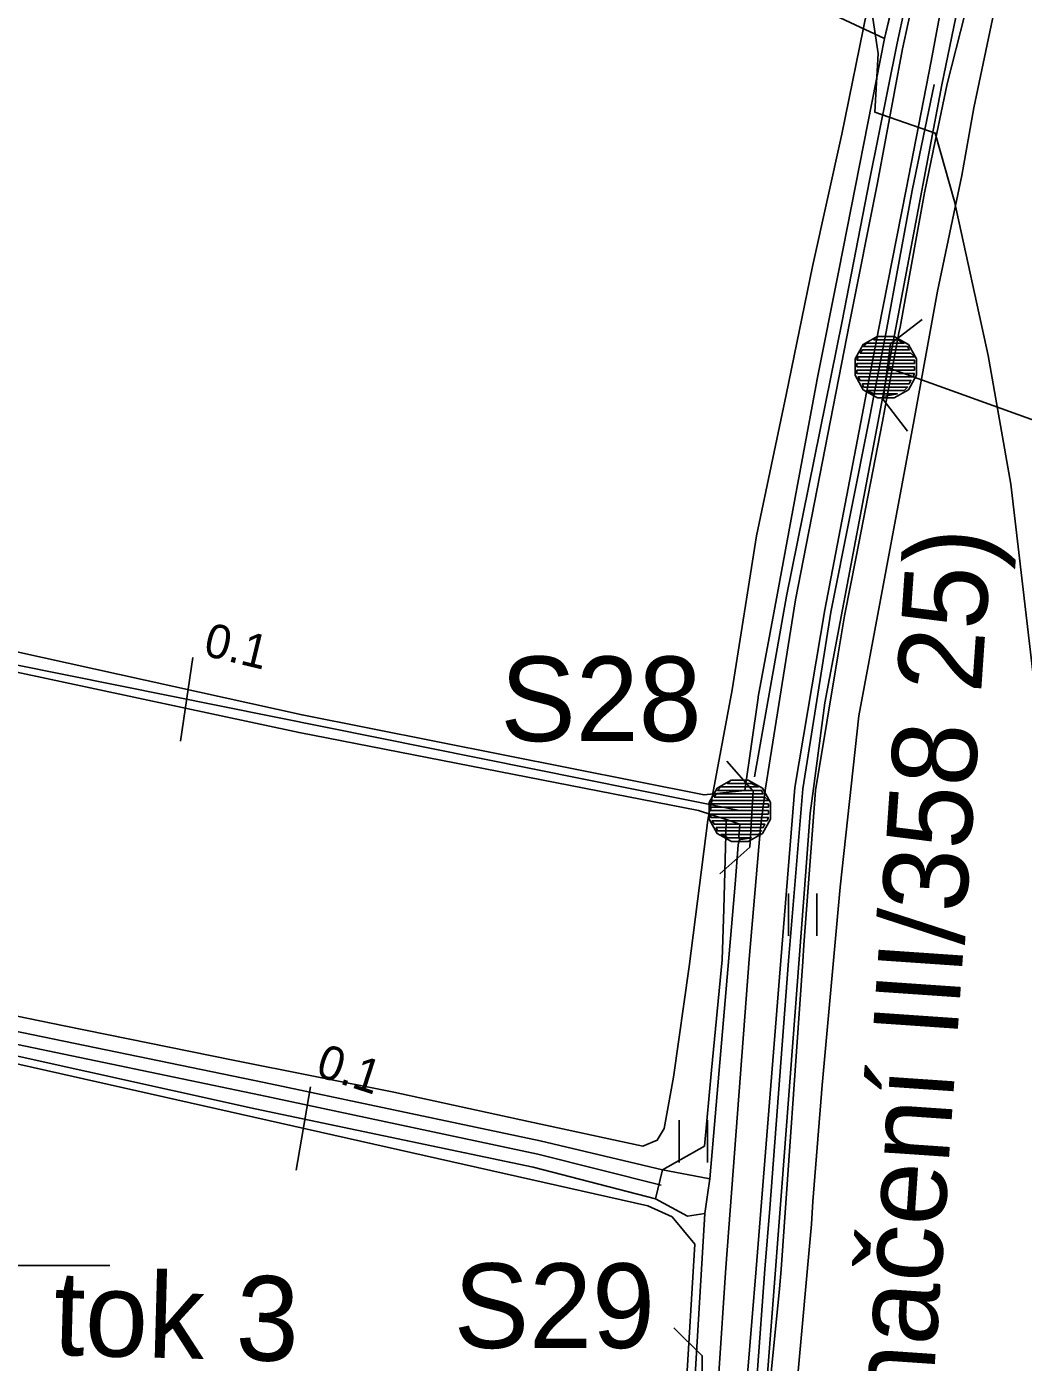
# Model space of a CAD drawing. Extents: x -645676 to -642474, y -1077513 to -1072613.
# Drawn here: x -644732.8 to -644556.1, y -1075319 to -1075082.2 of the extents above; entities that cross this region are included whole.
import ezdxf

# ---------------------------------------------------------------- set-up
doc = ezdxf.new("R2010")
doc.units = 0
for name, color, linetype in [('KULTURY_STAV', 7, 'Continuous'), ('KULTURY_ZNACKY', 7, 'Continuous'), ('NERESENE_POZEMKY', 7, 'Continuous'), ('Obvod_KP_', 7, 'Continuous'), ('OBVOD_PU', 7, 'Continuous'), ('P__kop___st_vaj_c_', 7, 'Continuous'), ('PC_NAVRH', 7, 'Continuous'), ('PC_OBJ_POPIS_NAVRH', 7, 'Continuous'), ('PC_OBJEKTY_NAVRH', 7, 'Continuous'), ('PC_STAN_NAVRH', 7, 'Continuous'), ('PLYNOVOD', 7, 'Continuous'), ('Popis_silnice_II__a_III__t__dy', 7, 'Continuous'), ('SDELOVACI', 7, 'Continuous'), ('Silnice_II__t__dy_a_III__t__dy', 7, 'Continuous'), ('Vodn__plocha___st_vaj_c_', 7, 'Continuous'), ('Vodn__tok', 7, 'Continuous'), ('VRSTEVNICE', 7, 'Continuous')]:
    doc.layers.add(name, color=color, linetype=linetype)

# ---------------------------------------------------------------- blocks, each defined once
blk = doc.blocks.new('$406')
blk.add_lwpolyline([(-0.19, 0.72), (0.2, 0.72), (0.54, 0.53), (0.73, 0.19), (0.73, -0.2), (0.54, -0.54), (0.2, -0.73), (-0.19, -0.73), (-0.53, -0.54), (-0.72, -0.2), (-0.72, 0.19), (-0.53, 0.53), (-0.2, 0.72), (-0.28, 0.64), (0.28, 0.64), (0.44, 0.56), (-0.44, 0.56), (-0.52, 0.48), (0.52, 0.48), (0.56, 0.4), (-0.55, 0.4), (-0.6, 0.32), (0.6, 0.32), (0.68, 0.24), (-0.59, 0.24), (-0.65, 0.24), (-0.68, 0.16), (0.59, 0.16), (0.68, 0.16), (0.68, 0.08), (-0.59, 0.08), (-0.68, 0.08), (-0.68, 0), (0.59, 0), (0.68, 0), (0.68, -0.08), (-0.59, -0.08), (-0.68, -0.08), (-0.68, -0.16), (0.59, -0.16), (0.68, -0.16), (0.65, -0.24), (-0.62, -0.24), (-0.65, -0.24), (-0.6, -0.32), (0.6, -0.32), (0.56, -0.4), (-0.55, -0.4), (-0.52, -0.48), (0.52, -0.48), (0.44, -0.56), (-0.44, -0.56), (-0.28, -0.64), (0.28, -0.64), (-0.02, -0.69)])
blk = doc.blocks.new('$944')
blk.add_line((0, 1.5), (0, -1.5))
blk = doc.blocks.new('8$0300')
for p, q in [((-7.5, 0), (-1.5, 0)), ((1.5, 0), (7.5, 0))]:
    blk.add_line(p, q)
blk = doc.blocks.new('3$0600')
for p, q in [((-0.5, 1.5), (-0.5, 0)), ((0.5, 0), (0.5, 1.5))]:
    blk.add_line(p, q)
blk = doc.blocks.new('$935')
blk.add_lwpolyline([(-2, -1), (-1, 0), (1, 0), (2, -1)])

msp = doc.modelspace()

# ---------------------------------------------------------------- linework, layer by layer
at = {"layer": 'KULTURY_STAV'}
for points in [[(-644641.24, -1075565.84), (-644614.92, -1075468.8), (-644611.62, -1075449.05), (-644602.57, -1075335.69), (-644598.94, -1075287.94), (-644594.67, -1075231.99), (-644593.88, -1075221.64), (-644593.31, -1075217.27), (-644591.32, -1075202.08), (-644570.53, -1075092.51), (-644563.77, -1075059.63)], [(-644563.77, -1075059.63), (-644570.53, -1075092.51), (-644591.32, -1075202.08), (-644593.31, -1075217.27), (-644593.88, -1075221.64), (-644594.67, -1075231.99), (-644598.94, -1075287.94), (-644602.57, -1075335.69), (-644611.62, -1075449.05), (-644614.92, -1075468.8), (-644641.24, -1075565.84)], [(-644563.36, -1075067.72), (-644569.63, -1075092.35), (-644571.75, -1075102.52), (-644573.65, -1075111.67), (-644575.07, -1075119.48), (-644577.96, -1075135.48), (-644578.15, -1075136.51), (-644578.57, -1075138.76), (-644581.06, -1075152.22), (-644585.75, -1075176.19), (-644587.8, -1075186.68), (-644588.91, -1075193.38), (-644592.93, -1075217.6), (-644595, -1075244.96), (-644595.22, -1075247.9), (-644599.01, -1075302.53), (-644599.35, -1075305.97), (-644600.88, -1075321.39)], [(-644600.88, -1075321.39), (-644599.35, -1075305.97), (-644599.01, -1075302.53), (-644595.22, -1075247.9), (-644595, -1075244.96), (-644592.93, -1075217.6), (-644588.91, -1075193.38), (-644587.8, -1075186.68), (-644585.75, -1075176.19), (-644581.06, -1075152.22), (-644578.57, -1075138.76), (-644578.15, -1075136.51), (-644577.96, -1075135.48), (-644575.07, -1075119.48), (-644573.65, -1075111.67), (-644571.75, -1075102.52), (-644569.63, -1075092.35), (-644563.36, -1075067.72)], [(-644734.54, -1075193.01), (-644683.98, -1075204.21), (-644612.72, -1075218.41), (-644605.49, -1075217.61), (-644603.14, -1075201.2), (-644603.12, -1075201.03), (-644599.69, -1075182.62), (-644596.24, -1075164.08), (-644592.7, -1075145.05), (-644592.69, -1075145.02), (-644588.83, -1075125.47), (-644580.71, -1075084.33), (-644577.57, -1075071.27)], [(-644577.57, -1075071.27), (-644580.71, -1075084.33), (-644588.83, -1075125.47), (-644592.69, -1075145.02), (-644592.7, -1075145.05), (-644596.24, -1075164.08), (-644599.69, -1075182.62), (-644603.12, -1075201.03), (-644603.14, -1075201.2), (-644605.49, -1075217.61), (-644612.72, -1075218.41), (-644683.98, -1075204.21), (-644734.54, -1075193.01)], [(-644735.38, -1075196.48), (-644684.51, -1075207.35), (-644613.68, -1075221.14), (-644608.8, -1075222.77), (-644608.87, -1075225.5), (-644609.23, -1075238.59), (-644609.48, -1075247.63), (-644611.37, -1075267.21), (-644612.66, -1075280.65), (-644620.07, -1075284.83), (-644641.76, -1075279.73), (-644690.73, -1075269.38), (-644741.2, -1075258.95)], [(-644616.89, -1075364.66), (-644612.56, -1075292.62), (-644612.08, -1075289.3), (-644611.68, -1075286.48), (-644607.21, -1075234.23), (-644606.65, -1075227.27), (-644606.36, -1075226.01), (-644606.54, -1075225.97), (-644606.35, -1075223.59), (-644608.8, -1075222.77), (-644613.68, -1075221.14), (-644684.51, -1075207.35), (-644735.38, -1075196.48)], [(-644608.8, -1075222.77), (-644606.35, -1075223.59), (-644606.54, -1075225.97), (-644606.36, -1075226.01), (-644606.65, -1075227.27), (-644607.21, -1075234.23), (-644611.68, -1075286.48), (-644611.99, -1075286.42), (-644620.07, -1075284.83), (-644612.66, -1075280.65), (-644611.37, -1075267.21), (-644609.48, -1075247.63), (-644609.23, -1075238.59), (-644608.87, -1075225.5), (-644608.8, -1075222.77)], [(-644741.2, -1075258.95), (-644690.73, -1075269.38), (-644641.76, -1075279.73), (-644620.07, -1075284.83), (-644611.99, -1075286.42), (-644611.68, -1075286.48), (-644612.08, -1075289.3), (-644612.56, -1075292.62), (-644615.66, -1075293.05), (-644621.33, -1075289.98), (-644643, -1075284.37), (-644655.11, -1075281.83), (-644692.33, -1075274.04), (-644736.8, -1075264.15)], [(-644851.08, -1075513.74), (-644779.52, -1075365.17), (-644777.84, -1075361.69), (-644757.68, -1075319.84), (-644760.71, -1075318.03), (-644746.53, -1075289.08), (-644737.59, -1075267.05), (-644736.8, -1075264.15), (-644692.33, -1075274.04), (-644655.11, -1075281.83), (-644643, -1075284.37), (-644621.33, -1075289.98), (-644615.66, -1075293.05), (-644612.56, -1075292.62), (-644616.89, -1075364.66), (-644616.92, -1075365.04), (-644618.52, -1075388.88), (-644622.17, -1075442.97), (-644622.41, -1075446.47), (-644626.67, -1075468.75), (-644631.36, -1075486.14), (-644660.63, -1075594.71)]]:
    msp.add_lwpolyline(points, dxfattribs=at)
at = {"layer": 'NERESENE_POZEMKY'}
msp.add_lwpolyline([(-644626.35, -1075010.4), (-644585.55, -1075012.13), (-644571.87, -1075012.71), (-644572.25, -1075021.71), (-644572.97, -1075038.79), (-644574.31, -1075056.6), (-644575.15, -1075060.82), (-644577.57, -1075071.27), (-644580.71, -1075084.33), (-644636.16, -1075058.45), (-644631.17, -1075036.69), (-644626.35, -1075010.4)], dxfattribs=at)
at = {"layer": 'Obvod_KP_'}
msp.add_lwpolyline([(-644626.35, -1075010.4), (-644631.17, -1075036.69), (-644636.16, -1075058.45), (-644580.71, -1075084.33), (-644575.15, -1075060.82), (-644574.31, -1075056.6), (-644572.97, -1075038.79), (-644572.25, -1075021.71), (-644571.87, -1075012.71)], close=True, dxfattribs=at)
at = {"layer": 'OBVOD_PU'}
msp.add_lwpolyline([(-644631.17, -1075036.69), (-644626.35, -1075010.4), (-644571.87, -1075012.71), (-644572.25, -1075021.71), (-644572.97, -1075038.79), (-644574.31, -1075056.6), (-644575.15, -1075060.82), (-644580.71, -1075084.33), (-644636.16, -1075058.45), (-644631.17, -1075036.69)], dxfattribs=at)
at = {"layer": 'P__kop___st_vaj_c_'}
for points in [[(-644575.75, -1075072.55), (-644578.46, -1075085.14), (-644583.36, -1075109.48), (-644588.22, -1075134.43), (-644598.09, -1075183.17), (-644603.76, -1075215.2)], [(-644655.14, -1075609.48), (-644653.46, -1075602.68), (-644648.86, -1075585.89), (-644635.16, -1075537.38), (-644617.89, -1075475.06), (-644613.54, -1075454.44), (-644610.92, -1075431.54), (-644607.37, -1075383.08), (-644603.3, -1075321.13), (-644601.93, -1075302.47), (-644601.06, -1075291.71), (-644597.72, -1075247.83), (-644595.19, -1075217.3), (-644590.26, -1075186), (-644583.34, -1075151.35), (-644580.44, -1075136.31), (-644575.79, -1075111.27), (-644571.92, -1075092.46)]]:
    msp.add_lwpolyline(points, dxfattribs=at)
at = {"layer": 'PC_NAVRH'}
for points in [[(-644606.41, -1075221.19), (-644836.11, -1075174.98), (-644844.56, -1075176.95), (-644881.27, -1075159.75), (-644907.13, -1075151.69), (-644922.26, -1075148.52), (-644947.39, -1075148.27), (-644953.49, -1075145.83), (-644953.49, -1075141.93), (-644894.93, -1074992.28), (-644829.47, -1074825.22)], [(-644615.94, -1075324.38), (-644614.35, -1075298.06), (-644618.37, -1075293.21), (-644622.69, -1075291.24), (-644738.79, -1075265.15), (-644794.9, -1075254.19), (-644881.17, -1075235.85), (-644890.64, -1075231.29), (-644935.93, -1075197.93), (-645029.58, -1075127.01), (-645122.98, -1075056.71), (-645236.69, -1074970.28), (-645321.72, -1074906.75)], [(-644580.52, -1075142.52), (-644416.45, -1075201.58), (-644177.18, -1075288.57), (-644151.16, -1075297.15), (-644120.06, -1075303.18), (-644089.59, -1075306.35), (-644066.74, -1075304.45)]]:
    msp.add_lwpolyline(points, dxfattribs=at)
at = {"layer": 'PLYNOVOD'}
msp.add_lwpolyline([(-644583.83, -1075079.56), (-644588.3, -1075101.28), (-644593.47, -1075124.74), (-644598.18, -1075147.46), (-644603.42, -1075172.45), (-644607.75, -1075199.77), (-644612.04, -1075222.9), (-644615.33, -1075248.82), (-644618.1, -1075268.44), (-644619.81, -1075277.52), (-644621, -1075279.62), (-644623.56, -1075280.66), (-644643.86, -1075276.28), (-644667.72, -1075271.06), (-644696.22, -1075265.41), (-644726.18, -1075259.33), (-644751.5, -1075254.12)], dxfattribs=at)
at = {"layer": 'SDELOVACI'}
msp.add_lwpolyline([(-644560.38, -1075075.22), (-644564.89, -1075096.59), (-644567.03, -1075108.6), (-644571.32, -1075129.12), (-644575.46, -1075151.85), (-644577.56, -1075163.27), (-644585.27, -1075204.39), (-644588.56, -1075234.74), (-644591.74, -1075269.83), (-644593.41, -1075290.49), (-644593.66, -1075294.47), (-644596.25, -1075323.14), (-644596.67, -1075334.53), (-644597.63, -1075356.25), (-644600.03, -1075389.03), (-644602.22, -1075418.8), (-644603.31, -1075432), (-644604.47, -1075443.16), (-644607.26, -1075459.62), (-644610.89, -1075475.88), (-644617.87, -1075501.8)], dxfattribs=at)
at = {"layer": 'Silnice_II__t__dy_a_III__t__dy'}
for p, q in [((-644567.71, -1075062.93), (-644572.45, -1075088.32)), ((-644577.5, -1075086.15), (-644574.76, -1075073.27)), ((-644577.5, -1075086.15), (-644574.76, -1075073.27)), ((-644581.97, -1075109.9), (-644577.5, -1075086.15)), ((-644572.45, -1075088.32), (-644576.86, -1075111.1)), ((-644586.92, -1075134.77), (-644581.97, -1075109.9)), ((-644576.86, -1075111.1), (-644581.76, -1075135.96)), ((-644596.48, -1075183.83), (-644586.92, -1075134.77)), ((-644581.76, -1075135.96), (-644584.65, -1075151.06)), ((-644584.65, -1075151.06), (-644591.32, -1075185.61)), ((-644601.8, -1075217.2), (-644596.48, -1075183.83)), ((-644591.32, -1075185.61), (-644596.6, -1075217.06)), ((-644601.8, -1075217.2), (-644602.73, -1075224.15)), ((-644596.6, -1075217.06), (-644599.09, -1075247.75)), ((-644604.74, -1075247.52), (-644602.73, -1075224.15)), ((-644608.84, -1075302.23), (-644604.74, -1075247.52)), ((-644599.09, -1075247.75), (-644603.5, -1075302.41)), ((-644610.11, -1075320.89), (-644608.84, -1075302.23)), ((-644605.01, -1075321.1), (-644603.5, -1075302.41))]:
    msp.add_line(p, q, dxfattribs=at)
at = {"layer": 'Vodn__plocha___st_vaj_c_'}
for points in [[(-644741.2, -1075258.95), (-644690.73, -1075269.38), (-644641.76, -1075279.73), (-644620.07, -1075284.83), (-644621.33, -1075289.98), (-644643, -1075284.37), (-644692.33, -1075274.04), (-644736.8, -1075264.15)], [(-644736.8, -1075264.15), (-644692.33, -1075274.04), (-644643, -1075284.37), (-644621.33, -1075289.98), (-644620.07, -1075284.83), (-644641.76, -1075279.73), (-644690.73, -1075269.38), (-644741.2, -1075258.95)]]:
    msp.add_lwpolyline(points, dxfattribs=at)
at = {"layer": 'Vodn__tok'}
msp.add_lwpolyline([(-644620.31, -1075287.58), (-644642.19, -1075282.08), (-644691.33, -1075271.61), (-644737.28, -1075262.07)], dxfattribs=at)
at = {"layer": 'VRSTEVNICE'}
msp.add_lwpolyline([(-644529.37, -1075309.13), (-644538.12, -1075291.51), (-644545.68, -1075259.97), (-644549.51, -1075238.53), (-644558.34, -1075163.33), (-644562.33, -1075140.54), (-644568.31, -1075113.2), (-644571.73, -1075101.09), (-644582.41, -1075097.39), (-644581.84, -1075086.99), (-644583.27, -1075077.59)], dxfattribs=at)

# ---------------------------------------------------------------- block references
at = {"layer": 'KULTURY_ZNACKY', "xscale": 5, "yscale": 5}
for name, p in [('3$0600', (-644595.21, -1075243.35)), ('3$0600', (-644614.63, -1075283.57)), ('8$0300', (-644755.6, -1075301.81))]:
    msp.add_blockref(name, p, dxfattribs=at)
at = {"layer": 'PC_OBJEKTY_NAVRH'}
for p, xscale, yscale, rotation in [((-644580.29, -1075143.38), 5, 4.999999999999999, 82.430234), ((-644604.3, -1075222.7), 5, 4.999999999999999, -93.52998600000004), ((-644613.03, -1075322.82), 4.999999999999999, 5.000000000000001, -89.857368)]:
    msp.add_blockref('$935', p, dxfattribs=dict(at, xscale=xscale, yscale=yscale, rotation=rotation))
at = {"layer": 'PC_STAN_NAVRH', "xscale": 7.5, "yscale": 7.5}
for p in [(-644580.52, -1075142.52), (-644606.41, -1075221.19)]:
    msp.add_blockref('$406', p, dxfattribs=at)
at = {"layer": 'PC_STAN_NAVRH'}
for p, xscale, yscale, rotation in [((-644704.45, -1075201.47), 5, 5, 171.570307), ((-644683.75, -1075277.52), 5.000000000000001, 4.999999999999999, 170.25864999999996)]:
    msp.add_blockref('$944', p, dxfattribs=dict(at, xscale=xscale, yscale=yscale, rotation=rotation))

# ---------------------------------------------------------------- texts
at = {"layer": 'PC_OBJ_POPIS_NAVRH'}
for s, p in [('S28', (-644648.84, -1075208.87)), ('S29', (-644657.11, -1075316.44))]:
    msp.add_text(s, height=15, dxfattribs=at).set_placement(p)
at = {"layer": 'PC_STAN_NAVRH'}
for rotation, p in [(346.525, (-644701.69, -1075193.62)), (341.999, (-644681.8, -1075268.12))]:
    msp.add_text('0.1', height=6, rotation=rotation, dxfattribs=at).set_placement(p)
at = {"layer": 'Popis_silnice_II__a_III__t__dy'}
msp.add_text('III/3583 (nové označení III/358 25)', height=15, rotation=86.058, dxfattribs=at).set_placement((-644582.62, -1075476.41))
at = {"layer": 'Vodn__tok'}
msp.add_text('tok 3', height=15, rotation=358.453, dxfattribs=at).set_placement((-644728.19, -1075317.66))

doc.saveas('drawing.dxf')
